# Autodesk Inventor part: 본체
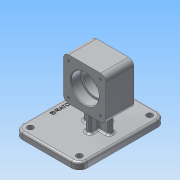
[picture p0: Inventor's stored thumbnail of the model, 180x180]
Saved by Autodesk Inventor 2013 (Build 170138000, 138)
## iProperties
Created: 2020-11
Part Number: 본체
Material: 알루미늄 6061
Document SubType Name: Modeling
Designer: Administrator
Density: 2.71 g/cm^3
Mass: 685.745 g
Surface Area: 542.794 cm^2
Volume: 253.042 cm^3
Author: Administrator
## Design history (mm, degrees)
sketch "스케치1"
  geometry: L1 (65, -49)-(-65, -49); L2 (-65, -49)-(-65, 49); L3 (-65, 49)-(65, 49); L4 (65, 49)-(65, -49); L5 (65, -49)-(-65, 49); L6 (-65, -49)-(65, 49); 1 further point
  constraints: 12 end point, 2 midpoint, 2 parallel, 1 horizontal, 1 perpendicular
  dimensions: "d0" = 130 distance of L2.end L3.end; "d2" = 98 distance between parallel lines of L3 L1
extrude "돌출1" new body sketch "스케치1" distance "d3" = 10; taper "d4" = 0 deg
fillet "모깎기1" dims "d5" = 12
node "작업 평면2"
sketch "스케치3"
  geometry: L1 (21, 70)-(85, 70); L2 (0, 0)-(106, 0) reference; L3 (74, 38)-(32, 38); L4 (32, 38)-(32, 102); L5 (32, 102)-(74, 102); L6 (74, 102)-(74, 38); L7 (74, 38)-(32, 102); L8 (32, 38)-(74, 102); 3 further points
  constraints: 14 end point, 4 midpoint, 2 horizontal, 2 parallel, 1 perpendicular, 1 vertical alignment
  dimensions: "d9" = 70 distance between parallel lines of L2 L1; "d10" = 64 distance of L1.start L1.end; "d13" = 64 distance between parallel lines of L3 L5; "d14" = 42 distance between parallel lines of L6 L4
extrude "돌출2" join sketch "스케치3" stored distance "d15" = 64; taper "d16" = 0 deg
node "작업 평면3"
sketch "스케치6"
  geometry: L1 (-38, -8)-(-38, 56) reference; L2 (-10, -12)-(-10, 0) reference; L3 (-10, 74)-(-10, 0) reference; L4 (-38, 24)-(-10, 24); L5 (-10, 24)-(-10, 4); L6 (-10, 24)-(-10, 44); L7 (-10, 44)-(-40.592, 44); L8 (-40.592, 44)-(-40.592, 4); L9 (-10, 4)-(-40.592, 4); 1 further point
  constraints: 12 end point, 3 perpendicular, 3 point on line, 1 midpoint, 1 parallel
  dimensions: "d18" = 20 distance of L4.end L5.end; "d19" = 20 distance of L4.end L6.end; "d20" = 30.59241 distance of L8.end L5.end
extrude "돌출3" join sketch "스케치6" stored distance "d22" = 8; taper "d23" = 0 deg
node "작업 평면4"
node "작업 평면5"
sketch "스케치7"
  geometry: L1 (32, 102)-(74, 102) reference; L2 (74, 38)-(32, 38) reference; L3 (106, 10)-(0, 10) reference; L4 (36, 10)-(70, 10); L5 (36, 10)-(36, 39.712); L6 (70, 10)-(70, 39.712); L7 (70, 39.712)-(36, 39.712); 3 further points
  constraints: 8 end point, 2 midpoint, 2 perpendicular, 2 point on line, 1 vertical alignment
  dimensions: "d24" = 34 distance of L4.start L4.end; "d109" = 34 distance of L6.end L5.end; "d110" = 29.71183 distance of L4.end L6.end
extrude "돌출4" join sketch "스케치7" stored distance "d27" = 8; taper "d28" = 0 deg
sketch "스케치8"
  geometry: L1 (0, 0)-(0, 64) reference; L2 (64, 0)-(0, 0) reference; L3 (64, 64)-(64, 0) reference; L4 (0, 64)-(64, 64) reference; L5 (0, 64)-(64, 64) reference; C1 r 21 at (32, 32); 4 further points
  constraints: 3 midpoint, 1 centre point, 1 horizontal alignment, 1 vertical alignment
  dimensions: "d29" = 42 diameter of C1
extrude "돌출5" cut sketch "스케치8" distance "d31" = 15; taper "d32" = 0 deg
sketch "스케치9"
  geometry: C1 r 21 at (0, 0) reference; C2 r 18 at (0, 0); 1 further point
  constraints: 1 centre point, 1 coincident
  dimensions: "d33" = 36 diameter of C2
extrude "돌출6" cut sketch "스케치9" distance "d36" = 12; taper "d37" = 0 deg
sketch "스케치10"
  geometry: C1 r 18 at (32, 32) reference; C2 r 21 at (32, 32); 1 further point
  constraints: 1 centre point, 1 coincident
  dimensions: "d38" = 42 diameter of C2
extrude "돌출7" cut sketch "스케치10" distance "d40" = 15; taper "d41" = 0 deg
fillet "모깎기2" dims "d42" = 0.3
chamfer "모따기1" distance "d43" = 1; stored, may be unused: second distance "d44" = 2, angle "d45" = 45 deg
fillet "모깎기3" dims "d46" = 3
sketch "스케치11"
  geometry: L1 (0, 0)-(0, 64) reference; L2 (64, 0)-(0, 0) reference; L3 (64, 0)-(64, 64) reference; L4 (0, 64)-(64, 64) reference; C1 r 22 at (32, 32) reference; 5 further points
  dimensions: "d47" = 24 horizontal distance of C1.centre point (56, 56); "d48" = 24 horizontal distance of C1.centre point (56, 56); "d49" = 48 distance of point (8, 56) point (56, 56); "d50" = 24 horizontal distance of C1.centre point (8, 56); "d51" = 48 distance of point (8, 56) point (8, 8); "d52" = 24 horizontal distance of C1.centre point (8, 8); "d53" = 48 distance of point (56, 8) point (8, 8); "d54" = 24 horizontal distance of point (56, 8) C1.centre
hole "구멍1" sketch "스케치11" at (56, 56), (56, 8), (8, 56), (8, 8) diameter "d55" = 3.242; stored, may be unused: countersink angle "d59" = 90 deg, drill point angle "d61" = 118 deg; dims "d56" = 8, "d57" = 4, "d58" = 2, "d60" = 10
node "작업 평면6"
hole "구멍2" diameter "d64" = 9; stored, may be unused: countersink angle "d68" = 90 deg, drill point angle "d70" = 0 deg; dims "d62" = 10, "d63" = 10, "d65" = 8, "d66" = 4, "d67" = 2, "d69" = 10
hole "구멍3" diameter "d73" = 9; stored, may be unused: countersink angle "d77" = 90 deg, drill point angle "d79" = 0 deg; dims "d71" = 10, "d72" = 10, "d74" = 8, "d75" = 4, "d76" = 2, "d78" = 10
hole "구멍4" diameter "d82" = 9; stored, may be unused: countersink angle "d86" = 90 deg, drill point angle "d88" = 0 deg; dims "d80" = 10, "d81" = 10, "d83" = 8, "d84" = 4, "d85" = 2, "d87" = 10
hole "구멍5" diameter "d91" = 9; stored, may be unused: countersink angle "d95" = 90 deg, drill point angle "d97" = 0 deg; dims "d89" = 10, "d90" = 10, "d92" = 8, "d93" = 4, "d94" = 2, "d96" = 10
fillet "모깎기5" dims "d99" = 3
fillet "모깎기8" dims "d102" = 8
sketch "스케치12"
  geometry: L1 (53, 49)-(-53, 49) reference; L2 (65, -37)-(65, 37) reference; 2 further points
  constraints: 1 other
  dimensions: "d103" = 10 distance from line of point (0, 39) L1; "d104" = 65 distance from line of point (0, 39) L2
feature "엠보싱1" sketch "스케치12" dims "d0" = 130, "d2" = 98, "d9" = 70, "d10" = 64, "d13" = 64, "d14" = 42, "d105" = 0.5, "d106" = 0
fillet "모깎기11" dims "d111" = 3
fillet "모깎기12" dims "d112" = 3
node "솔리드1"
mirror "대칭1"
node "투영된 루프1"
node "투영된 루프2"
node "투영된 루프3"
other parameters: "d7" = -62, "d17" = -65
